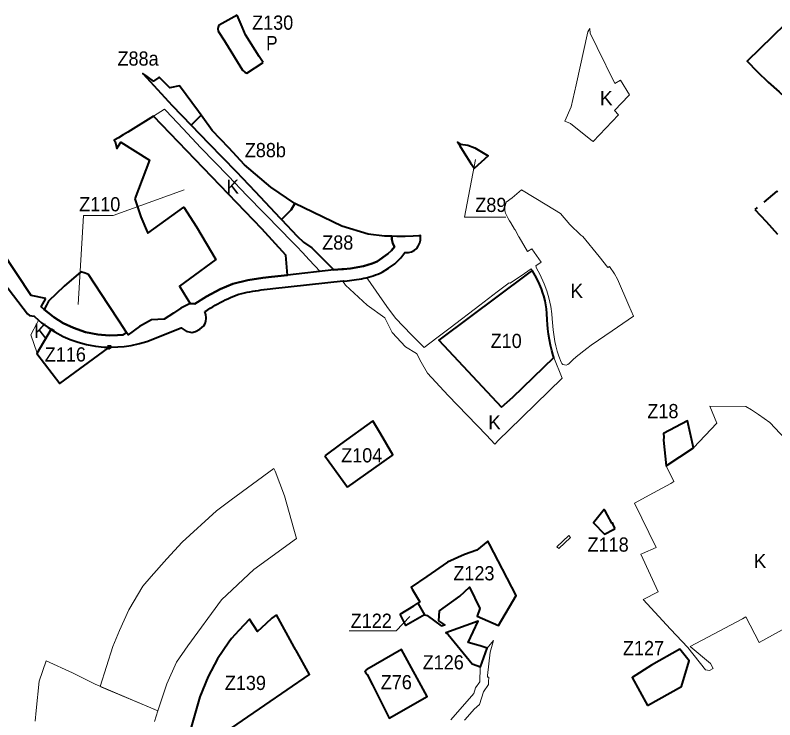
# Model space of a CAD drawing. Extents: x -650276 to -642489, y -1074311 to -1066658.
# Drawn here: x -647428 to -646145, y -1072934 to -1071744 of the extents above; entities that cross this region are included whole.
import ezdxf

# ---------------------------------------------------------------- set-up
doc = ezdxf.new("R2010")
doc.units = 0
doc.header["$LTSCALE"] = 9.6
doc.linetypes.add('MEDIUM_DASHED', pattern=[4.5, 3, -1.5])
for name, color, linetype, lineweight in [('2', 7, 'Continuous', 40), ('4', 7, 'Continuous', 40), ('44', 7, 'Continuous', 40), ('45', 7, 'Continuous', 40), ('46', 7, 'Continuous', 13), ('47', 7, 'Continuous', 13), ('48', 7, 'Continuous', 35), ('59', 7, 'Continuous', 13), ('60', 7, 'Continuous', 35), ('61', 7, 'MEDIUM_DASHED', 40)]:
    doc.layers.add(name, color=color, linetype=linetype, lineweight=lineweight)

msp = doc.modelspace()

# ---------------------------------------------------------------- linework, layer by layer
at = {"layer": '2'}
for points in [[(-647053.43, -1071743.63), (-647083.97, -1071760.74), (-647084.95, -1071761.98), (-647085.71, -1071763.75), (-647086.19, -1071766.95), (-647085.25, -1071770.69), (-647074.99, -1071786.99), (-647073.19, -1071789.9), (-647044.12, -1071836.68)], [(-647009.514, -1071823.81), (-647016.12, -1071813.35), (-647039.14, -1071776.9), (-647044.83, -1071763.37), (-647053.43, -1071743.63)], [(-647044.12, -1071836.68), (-647040.2, -1071839.6), (-647037.23, -1071841.82), (-647009.514, -1071823.81)], [(-647184.81, -1071848.61), (-647185.62, -1071849.12), (-647194.96, -1071854.93), (-647205.62, -1071847.24), (-647212.66, -1071842.15), (-647163.08, -1071896.13), (-647131.146, -1071929.146)], [(-647131.146, -1071929.146), (-647114.479, -1071912.479), (-647118.79, -1071906.59), (-647151.07, -1071863.08), (-647167.15, -1071866.22), (-647184.81, -1071848.61)], [(-646996.8, -1072034.35), (-647040.89, -1071996.58), (-647067.53, -1071967.54), (-647095.51, -1071938.39), (-647114.479, -1071912.479), (-647131.146, -1071929.146), (-647101.07, -1071960.24)], [(-647101.07, -1071960.24), (-647055.16, -1072007.74), (-647023.04, -1072041.63), (-646981.35, -1072085.77), (-646978.602, -1072088.66), (-646962.041, -1072072.379), (-646956.04, -1072061.95), (-646996.8, -1072034.35)], [(-646737.05, -1072756.4), (-646732.5, -1072757.63), (-646708.65, -1072775.02), (-646702.45, -1072773.39), (-646712.46, -1072766.76), (-646711.79, -1072750.02), (-646677.39, -1072724.85), (-646660.89, -1072709.97), (-646643.36, -1072746.04), (-646647.93, -1072759.01), (-646612.11, -1072774.56), (-646581.92, -1072723.91), (-646589.37, -1072709.83), (-646605.23, -1072679.37), (-646627.32, -1072636.95), (-646629.86, -1072632.07), (-646648.27, -1072647.48), (-646669.6, -1072654.53), (-646697.89, -1072667.65)], [(-646697.89, -1072667.65), (-646732.95, -1072691.68), (-646759.491, -1072709.878), (-646757.5, -1072713.3), (-646747.87, -1072729.85), (-646744.94, -1072734.88), (-646748.3, -1072737.01), (-646737.05, -1072756.4)], [(-646653.02, -1072806.07), (-646663.07, -1072803.04), (-646663.07, -1072803.04), (-646646.12, -1072767.32), (-646646.31, -1072767.388), (-646701.12, -1072787.08), (-646697.09, -1072790.03), (-646656.36, -1072839.08)], [(-646656.36, -1072839.08), (-646642.404, -1072844.195), (-646631.08, -1072812.68), (-646643.01, -1072809.08), (-646651.11, -1072806.64), (-646653.02, -1072806.07)]]:
    msp.add_lwpolyline(points, dxfattribs=at)
for points in [[(-646778.2, -1072755.19), (-646755.1, -1072741.28), (-646748.3, -1072737.01), (-646737.05, -1072756.4), (-646768.74, -1072774.78)], [(-646360.22, -1072909.57), (-646303.02, -1072877.74), (-646289.63, -1072834.04), (-646305.56, -1072814.43), (-646353.25, -1072841.63), (-646385.86, -1072862.59)]]:
    msp.add_lwpolyline(points, close=True, dxfattribs=at)
at = {"layer": '4'}
for points in [[(-646987.154, -1072756.377), (-646995.02, -1072762.45), (-647005.249, -1072771.938), (-647019.06, -1072784.57), (-647032.7, -1072763.68), (-647050.492, -1072782.771)], [(-646954.7, -1072815.232), (-646957.105, -1072810.92), (-646987.154, -1072756.377)], [(-647050.492, -1072782.771), (-647063.04, -1072796.74), (-647067.22, -1072802.77), (-647086.65, -1072830.76), (-647102.38, -1072860.7), (-647116.33, -1072895.3)], [(-647136.39, -1072968.63), (-647110.32, -1072964.56), (-647107.01, -1072964.04), (-647105.4, -1072963.84), (-647082.36, -1072960.95), (-646931.1, -1072857.55), (-646954.51, -1072815.63), (-646954.7, -1072815.232)], [(-647116.33, -1072895.3), (-647132.47, -1072950.4), (-647136.39, -1072968.63)]]:
    msp.add_lwpolyline(points, dxfattribs=at)
at = {"layer": '44'}
msp.add_line((-646978.602, -1072088.66), (-646951.95, -1072116.84), dxfattribs=at)
msp.add_lwpolyline([(-646652.18, -1071967.73), (-646629.655, -1071981.343), (-646653.198, -1072002.544), (-646657.32, -1071995.98), (-646658.79, -1071993.62), (-646669.31, -1071976.77), (-646676.79, -1071964.97), (-646681.07, -1071958.16), (-646675.99, -1071961.64), (-646663.87, -1071963.26)], close=True, dxfattribs=at)
at = {"layer": '44', "lineweight": 13}
msp.add_lwpolyline([(-646599.686, -1072084.891), (-646669.193, -1072084.891), (-646650.508, -1071987.658)], dxfattribs=at)
msp.add_lwpolyline([(-646599.686, -1072084.891), (-646669.193, -1072084.891), (-646650.508, -1071987.658)], dxfattribs=at)
at = {"layer": '44'}
for points in [[(-646790.432, -1072129.195), (-646791.977, -1072122.305), (-646791.84, -1072117.172), (-646804.27, -1072116.98), (-646832.01, -1072113.66), (-646876.83, -1072100.12), (-646941.054, -1072069.172), (-646956.04, -1072061.95), (-646962.041, -1072072.379), (-646978.602, -1072088.66)], [(-646951.95, -1072116.84), (-646941.45, -1072126.84), (-646927.14, -1072136.74), (-646891.05, -1072172.79), (-646890.044, -1072174.056), (-646876.712, -1072172.592), (-646873.495, -1072172.799), (-646862.09, -1072171.444), (-646840.102, -1072167.623), (-646825.169, -1072163.164), (-646816.74, -1072159.571), (-646799, -1072147), (-646792.58, -1072140.847), (-646787.481, -1072134.643), (-646790.432, -1072129.195)], [(-646808.466, -1072177.78), (-646797.713, -1072171.151), (-646787.223, -1072163.402), (-646777.129, -1072153.576), (-646770.057, -1072144.677), (-646763.959, -1072144.535), (-646758.736, -1072143.137), (-646753.929, -1072140.612), (-646750.164, -1072137.467), (-646747.39, -1072134.069), (-646744.554, -1072128.415), (-646743.411, -1072123.612), (-646743.596, -1072115.985), (-646746.547, -1072116.221), (-646756.298, -1072117), (-646769.668, -1072117.517), (-646783.449, -1072117.302), (-646791.84, -1072117.172)], [(-646791.84, -1072117.172), (-646791.977, -1072122.305), (-646790.432, -1072129.195)], [(-646790.432, -1072129.195), (-646787.481, -1072134.643), (-646792.58, -1072140.847), (-646799, -1072147), (-646816.74, -1072159.571), (-646825.169, -1072163.164), (-646840.102, -1072167.623), (-646862.09, -1072171.444), (-646873.495, -1072172.799), (-646876.712, -1072172.592), (-646890.044, -1072174.056), (-646968.503, -1072182.672)], [(-647376.68, -1072222.29), (-647401.221, -1072217.342), (-647451.21, -1072142.08), (-647452.23, -1072134.91)], [(-647475.57, -1072159.74), (-647447.73, -1072195.72), (-647407.34, -1072247.93)], [(-646835.538, -1072187.097), (-646831.517, -1072186.103), (-646827.501, -1072184.997), (-646823.496, -1072183.769), (-646819.509, -1072182.408), (-646815.549, -1072180.906), (-646811.621, -1072179.254), (-646808.466, -1072177.78)], [(-646968.503, -1072182.672), (-646995.137, -1072185.597), (-647010.148, -1072187.308), (-647035.515, -1072191.104), (-647060.973, -1072197.439), (-647082.249, -1072206.591), (-647104.989, -1072219.005), (-647124.81, -1072231.168), (-647133, -1072230.754), (-647148.71, -1072238.76)], [(-647017.46, -1072208.427), (-647012.612, -1072207.773), (-647007.734, -1072207.162), (-647002.826, -1072206.583), (-646997.894, -1072206.024), (-646992.937, -1072205.475), (-646874.517, -1072192.471), (-646871.271, -1072192.675)], [(-646871.271, -1072192.675), (-646867.371, -1072192.234), (-646867.32, -1072192.228), (-646863.448, -1072191.771), (-646859.506, -1072191.276), (-646855.545, -1072190.741), (-646851.567, -1072190.155)], [(-646851.567, -1072190.155), (-646847.575, -1072189.507), (-646843.569, -1072188.789), (-646843.535, -1072188.782), (-646839.556, -1072187.988), (-646835.538, -1072187.097)], [(-647108.131, -1072244.373), (-647103.164, -1072241.306), (-647098.944, -1072238.718), (-647094.737, -1072236.177), (-647090.531, -1072233.695), (-647086.322, -1072231.285), (-647082.102, -1072228.962), (-647077.867, -1072226.739), (-647073.611, -1072224.631), (-647069.33, -1072222.651), (-647064.868, -1072220.746), (-647054.841, -1072216.479), (-647050.344, -1072215.107), (-647045.786, -1072213.858), (-647041.174, -1072212.723), (-647036.512, -1072211.693), (-647031.807, -1072210.758), (-647027.061, -1072209.91), (-647022.278, -1072209.136), (-647017.46, -1072208.427)], [(-647240.55, -1072279.42), (-647246.206, -1072283.328), (-647255.671, -1072284.192), (-647269.579, -1072284.489), (-647288.769, -1072283.003), (-647309.416, -1072278.875), (-647330.032, -1072271.935), (-647347.382, -1072263.623), (-647363.317, -1072253.632), (-647363.786, -1072253.254), (-647379.422, -1072240.675), (-647384.567, -1072236.256), (-647376.68, -1072222.29)], [(-647148.71, -1072238.76), (-647160.91, -1072246.82), (-647176.7, -1072257.24), (-647198.3, -1072258.09), (-647218.35, -1072269.67), (-647237.6, -1072283.78), (-647240.55, -1072279.42)], [(-647407.34, -1072247.93), (-647404.45, -1072250.66), (-647396.25, -1072252.14), (-647389.072, -1072258.845)], [(-647389.072, -1072258.845), (-647383.813, -1072263.219), (-647372.858, -1072271.363), (-647361.521, -1072278.584), (-647347.369, -1072286.111)], [(-647205.975, -1072294.599), (-647148.171, -1072271.47), (-647139.697, -1072277.484), (-647130.12, -1072279.44), (-647123.774, -1072277.899)], [(-647123.774, -1072277.899), (-647116.323, -1072273.885), (-647109.812, -1072268.588)], [(-647347.369, -1072286.111), (-647335.382, -1072291.341), (-647321.953, -1072296.073), (-647308.157, -1072299.786), (-647292.715, -1072302.646), (-647278.108, -1072304.147), (-647271.395, -1072304.452), (-647269.52, -1072307.17), (-647265.793, -1072304.439)], [(-647265.793, -1072304.439), (-647255.16, -1072304.123), (-647244.428, -1072303.192), (-647232.368, -1072301.4), (-647218.5, -1072298.335), (-647205.975, -1072294.599)]]:
    msp.add_lwpolyline(points, dxfattribs=at)
msp.add_arc((-647130.12, -1072255.012), 24.428, 326.23773, 25.81772, dxfattribs=at)
at = {"layer": '45'}
msp.add_line((-646417.787, -1072612.168), (-646414.77, -1072610.61), dxfattribs=at)
for points in [[(-646102.04, -1071906.4), (-646068.317, -1071937.555), (-646062.91, -1071942.55), (-646002.93, -1071893.984), (-646026.64, -1071867.44), (-646043.49, -1071845.87), (-646077.32, -1071802.59), (-646087, -1071795), (-646104.5, -1071774.86), (-646122.16, -1071754.78), (-646127.12, -1071759.15), (-646127.84, -1071758.53), (-646191.57, -1071821.44), (-646174.69, -1071838.69), (-646156.59, -1071856.53), (-646137.74, -1071873.31)], [(-647226.41, -1072054.11), (-647219.64, -1072074.29), (-647216.23, -1072084.14), (-647204.78, -1072110.92), (-647204.38, -1072111.87), (-647143.76, -1072067.69), (-647122.33, -1072101.34), (-647089.54, -1072156.53), (-647134.17, -1072188.95), (-647151.05, -1072201.21), (-647138.65, -1072221.5), (-647133, -1072230.754), (-647124.81, -1072231.168), (-647104.989, -1072219.005), (-647082.249, -1072206.591), (-647060.973, -1072197.439), (-647035.515, -1072191.104), (-647010.148, -1072187.308), (-646995.137, -1072185.597), (-646968.503, -1072182.672), (-646971.283, -1072148.82), (-647011.762, -1072104.502), (-647194.903, -1071913.941), (-647238.1, -1071941), (-647245.71, -1071945.77), (-647253.67, -1071950.76), (-647261.12, -1071954.82), (-647259.7, -1071957.06), (-647256.53, -1071968.64), (-647253.85, -1071964.38), (-647249.92, -1071958.12), (-647201.53, -1071988.71)], [(-647226.41, -1072054.11), (-647219.64, -1072074.29), (-647216.23, -1072084.14), (-647204.78, -1072110.92), (-647204.38, -1072111.87), (-647143.76, -1072067.69), (-647122.33, -1072101.34), (-647089.54, -1072156.53), (-647134.17, -1072188.95), (-647151.05, -1072201.21), (-647138.65, -1072221.5), (-647133, -1072230.754), (-647124.81, -1072231.168), (-647104.989, -1072219.005), (-647082.249, -1072206.591), (-647060.973, -1072197.439), (-647035.515, -1072191.104), (-647010.148, -1072187.308), (-646995.137, -1072185.597), (-646968.503, -1072182.672), (-646971.283, -1072148.82), (-647011.762, -1072104.502), (-647194.903, -1071913.941), (-647238.1, -1071941), (-647245.71, -1071945.77), (-647253.67, -1071950.76), (-647261.12, -1071954.82), (-647259.7, -1071957.06), (-647256.53, -1071968.64), (-647253.85, -1071964.38), (-647249.92, -1071958.12), (-647201.53, -1071988.71)], [(-647246.563, -1072270.214), (-647251.85, -1072262.12), (-647271.38, -1072232.23), (-647304.32, -1072181.81), (-647310.33, -1072179.58), (-647317.33, -1072176.99), (-647345.42, -1072201.58), (-647372.1, -1072226.89), (-647375.551, -1072233.387), (-647379.422, -1072240.675), (-647363.317, -1072253.632), (-647347.382, -1072263.623), (-647330.032, -1072271.935), (-647309.416, -1072278.875), (-647288.769, -1072283.003), (-647269.579, -1072284.489), (-647255.671, -1072284.192), (-647246.206, -1072283.328), (-647240.55, -1072279.42)], [(-647246.563, -1072270.214), (-647251.85, -1072262.12), (-647271.38, -1072232.23), (-647304.32, -1072181.81), (-647310.33, -1072179.58), (-647317.33, -1072176.99), (-647345.42, -1072201.58), (-647372.1, -1072226.89), (-647375.551, -1072233.387), (-647379.422, -1072240.675), (-647363.317, -1072253.632), (-647347.382, -1072263.623), (-647330.032, -1072271.935), (-647309.416, -1072278.875), (-647288.769, -1072283.003), (-647269.579, -1072284.489), (-647255.671, -1072284.192), (-647246.206, -1072283.328), (-647240.55, -1072279.42)], [(-646606.848, -1072405.785), (-646587.666, -1072389.082), (-646518.208, -1072321.92), (-646519.417, -1072318.408), (-646522.007, -1072309.932), (-646524.282, -1072300.849), (-646526, -1072292.201), (-646527.5, -1072282.657), (-646528.566, -1072273.308), (-646529.182, -1072265.941), (-646529.607, -1072258.124), (-646530.188, -1072247.442), (-646530.892, -1072239.747), (-646531.93, -1072232.861), (-646533.286, -1072226.031), (-646535.344, -1072217.844), (-646536.772, -1072213.218), (-646539.168, -1072206.122), (-646539.168, -1072206.122), (-646542.484, -1072197.985), (-646546.09, -1072190.428), (-646549.793, -1072183.38), (-646554.56, -1072175.629), (-646555.051, -1072174.933), (-646563.299, -1072181.091), (-646710.684, -1072291.133), (-646712.634, -1072292.59)], [(-646333.34, -1072461.67), (-646328.45, -1072504.81), (-646282.47, -1072474.34), (-646292.44, -1072428.89), (-646333.33, -1072450.12), (-646332.68, -1072456.19)], [(-646333.34, -1072461.67), (-646328.45, -1072504.81), (-646282.47, -1072474.34), (-646292.44, -1072428.89), (-646333.33, -1072450.12), (-646332.68, -1072456.19)], [(-646837.81, -1072851.3), (-646836.5, -1072853.76), (-646833.67, -1072857.15), (-646824.89, -1072874.66), (-646796.68, -1072930.92), (-646732.28, -1072894.29), (-646775.85, -1072815.39), (-646834.08, -1072849.15)], [(-646837.81, -1072851.3), (-646836.5, -1072853.76), (-646833.67, -1072857.15), (-646824.89, -1072874.66), (-646796.68, -1072930.92), (-646732.28, -1072894.29), (-646775.85, -1072815.39), (-646834.08, -1072849.15)]]:
    msp.add_lwpolyline(points, close=True, dxfattribs=at)
for points in [[(-647362.702, -1072277.035), (-647367.686, -1072273.861), (-647391.761, -1072315.201), (-647353.041, -1072365.971), (-647270.701, -1072305.621), (-647266.974, -1072302.89), (-647272.576, -1072302.903)], [(-646824.42, -1072428.58), (-646878.91, -1072468.54), (-646905.18, -1072487.8)], [(-646824.42, -1072428.58), (-646878.91, -1072468.54), (-646905.18, -1072487.8)], [(-646867.283, -1072540.984), (-646791.569, -1072487.198), (-646790.354, -1072486.136), (-646810.77, -1072451.09), (-646824.42, -1072428.58)], [(-646867.283, -1072540.984), (-646791.569, -1072487.198), (-646790.354, -1072486.136), (-646810.77, -1072451.09), (-646824.42, -1072428.58)], [(-646905.18, -1072487.8), (-646898.1, -1072498.02), (-646893.64, -1072504.45), (-646867.283, -1072540.984)], [(-646905.18, -1072487.8), (-646898.1, -1072498.02), (-646893.64, -1072504.45), (-646867.283, -1072540.984)], [(-646420.36, -1072601.78), (-646427.95, -1072588.07), (-646432.57, -1072579.75), (-646433.36, -1072578.45), (-646451.458, -1072601.008), (-646433.024, -1072620.04), (-646417.787, -1072612.168)], [(-646414.77, -1072610.61), (-646419.11, -1072602.03), (-646419.47, -1072601.31), (-646419.02, -1072604.18), (-646420.36, -1072601.78)]]:
    msp.add_lwpolyline(points, dxfattribs=at)
msp.add_arc((-646767.624, -1072120.384), 24.428, 264.28146, 264.89913, dxfattribs=at)
msp.add_arc((-646767.624, -1072120.384), 24.428, 264.28146, 264.89913, dxfattribs=at)
at = {"layer": '46'}
for points in [[(-647321.863, -1072232.262), (-647313.149, -1072082.081), (-647262.801, -1072082.081), (-647142.741, -1072038.48)], [(-647321.863, -1072232.262), (-647313.149, -1072082.081), (-647262.801, -1072082.081), (-647142.741, -1072038.48)], [(-646864.278, -1072783.783), (-646784.878, -1072783.783), (-646761.687, -1072759.411)]]:
    msp.add_lwpolyline(points, dxfattribs=at)
at = {"layer": '47'}
for p, q in [((-646490.111, -1071926.754), (-646453.04, -1071956.3)), ((-647391.346, -1072314.489), (-647368.024, -1072274.442))]:
    msp.add_line(p, q, dxfattribs=at)
for points in [[(-646453.04, -1071956.3), (-646451.87, -1071956.88), (-646409.4, -1071912.17), (-646416.2, -1071904.81), (-646391.83, -1071879.32), (-646390.732, -1071878.171), (-646405.99, -1071853.26), (-646415.46, -1071859.05), (-646445.115, -1071798.418), (-646456.96, -1071774.2), (-646457.52, -1071765.98), (-646461.09, -1071771.76), (-646480.81, -1071861.18), (-646489.34, -1071898.61), (-646499.741, -1071922.455), (-646490.111, -1071926.754)], [(-646913.373, -1072176.618), (-646931.653, -1072156.802), (-646942.78, -1072144.74), (-646952.48, -1072134.22), (-646964.8, -1072121.83), (-646977.59, -1072108.96), (-646978.45, -1072108.09), (-647036.8, -1072048.41), (-647068.31, -1072015.68), (-647114.59, -1071967.77), (-647145.38, -1071935), (-647173.14, -1071905.45), (-647174.57, -1071904.06), (-647176.32, -1071902.3), (-647194.902, -1071913.942), (-647011.762, -1072104.502)], [(-646507.28, -1072078.4), (-646530.073, -1072064.559), (-646573.05, -1072038.46), (-646588.75, -1072052.06), (-646598.827, -1072059.244), (-646599.86, -1072063.71), (-646601, -1072067.55), (-646601.42, -1072071.01), (-646601.16, -1072074.07), (-646600.8, -1072075.94), (-646600.22, -1072077.86), (-646598.67, -1072081.55), (-646595.86, -1072086.82), (-646593.13, -1072091.01), (-646591.02, -1072094.4), (-646585.08, -1072104.81), (-646583.9, -1072106.42), (-646577.41, -1072117.76), (-646577.08, -1072118.7), (-646563.11, -1072143.03), (-646555.49, -1072138.17), (-646539.94, -1072160.83), (-646548.676, -1072166.737)], [(-646472.72, -1072115.38), (-646491.69, -1072097.45), (-646507.28, -1072078.4)], [(-647011.762, -1072104.502), (-646971.283, -1072148.82), (-646968.503, -1072182.672), (-646913.373, -1072176.618)], [(-646426.98, -1072169.74), (-646441.961, -1072151.281), (-646469.41, -1072117.44), (-646472.72, -1072115.38)], [(-646548.676, -1072166.737), (-646547.606, -1072170.835), (-646541.822, -1072181.102), (-646534.527, -1072197.411), (-646530.167, -1072209.31), (-646526.798, -1072221.011), (-646523.628, -1072235.883)], [(-646415.84, -1072180.43), (-646424.56, -1072167.96), (-646426.98, -1072169.74)], [(-646391.77, -1072233.91), (-646410.68, -1072189.36), (-646415.84, -1072180.43)], [(-646523.628, -1072235.883), (-646523.628, -1072235.883), (-646521.646, -1072248.378), (-646521.051, -1072256.707), (-646519.756, -1072274.861), (-646518.079, -1072287.051), (-646516.692, -1072294.983), (-646515.305, -1072301.925), (-646512.729, -1072311.048), (-646509.954, -1072319.377), (-646506.189, -1072329.889), (-646504.802, -1072331.971), (-646503.018, -1072333.459), (-646500.244, -1072334.45), (-646497.569, -1072334.55), (-646494.794, -1072333.558), (-646492.813, -1072332.07), (-646486.273, -1072325.526), (-646480.923, -1072320.667), (-646462.79, -1072306.784), (-646455.557, -1072301.131), (-646420.085, -1072276.737), (-646384.056, -1072252.138), (-646391.77, -1072233.91)], [(-647389.072, -1072258.845), (-647391.3, -1072263.04), (-647401.88, -1072283.4), (-647391.346, -1072314.489)], [(-647368.024, -1072274.442), (-647372.858, -1072271.363), (-647372.858, -1072271.363), (-647383.813, -1072263.219), (-647389.072, -1072258.845)], [(-645999.622, -1072714.927), (-646006.66, -1072681.4), (-646019.16, -1072642.35), (-646030.17, -1072612.31), (-646043.87, -1072578.12), (-646056.42, -1072556.49), (-646075.82, -1072525.54), (-646110.61, -1072477.49), (-646153.49, -1072431.54), (-646172.81, -1072418.2), (-646184.449, -1072410.256), (-646194.19, -1072404.62), (-646254.75, -1072404.25), (-646243.17, -1072432.88), (-646282.47, -1072474.34), (-646328.45, -1072504.81), (-646315.452, -1072531.573)], [(-646315.452, -1072531.573), (-646320.62, -1072534.6), (-646350.18, -1072550.59), (-646382.41, -1072568.01), (-646345.6, -1072642.55), (-646368.51, -1072652.81), (-646371.66, -1072654.2), (-646342.08, -1072717.43), (-646367.72, -1072730.68), (-646321.171, -1072780.535), (-646292.17, -1072811.6), (-646261.97, -1072849.66), (-646255.39, -1072850.83), (-646249.04, -1072847.16), (-646253.56, -1072838.8), (-646288.27, -1072810.22), (-646199.72, -1072763.1), (-646194.296, -1072760.193)], [(-646194.296, -1072760.193), (-646171.72, -1072803.51), (-646052.58, -1072737.82), (-646037.23, -1072736.38), (-646022.4, -1072741.58), (-646003.22, -1072757.85), (-645988.43, -1072769.93), (-645983.22, -1072780.88), (-645986.24, -1072788.33), (-645986.359, -1072796.127)], [(-646669.198, -1072934.569), (-646668.09, -1072933.43), (-646652.76, -1072915.66), (-646644.069, -1072908.218), (-646644.061, -1072908.209), (-646644.059, -1072908.208), (-646637.2, -1072886.57), (-646628.7, -1072874.5), (-646628.58, -1072869.88), (-646628.36, -1072861.71), (-646630.76, -1072861.61), (-646630.57, -1072859.99), (-646630.45, -1072858.93), (-646625.91, -1072819.66), (-646620.27, -1072799.95), (-646631.08, -1072812.68), (-646640.313, -1072838.394), (-646642.404, -1072844.195), (-646642.39, -1072844.2), (-646642.438, -1072844.29), (-646642.939, -1072845.68), (-646643.574, -1072869.57), (-646650.798, -1072879.828), (-646653.846, -1072889.44), (-646692.432, -1072934.135)], [(-647192.93, -1072936.82), (-647187.445, -1072918.804), (-647293.317, -1072873.549), (-647293.351, -1072873.533), (-647331.82, -1072854.49), (-647375.92, -1072833.99), (-647387.64, -1072868.69), (-647392.96, -1072918.277), (-647394.87, -1072936.08)]]:
    msp.add_lwpolyline(points, dxfattribs=at)
for points in [[(-646587.666, -1072389.082), (-646606.848, -1072405.785), (-646712.634, -1072292.59), (-646563.299, -1072181.091), (-646556.591, -1072176.083), (-646555.051, -1072174.933), (-646556.693, -1072172.16), (-646568.051, -1072179.84), (-646592.2, -1072196.17), (-646593.85, -1072195.48), (-646614.075, -1072210.952), (-646643.55, -1072233.5), (-646693.58, -1072271.606), (-646716.167, -1072288.809), (-646737.449, -1072305.019), (-646738.951, -1072303.49), (-646758.684, -1072283.41), (-646785.958, -1072255.505), (-646800.76, -1072235.668), (-646813.508, -1072217.089), (-646813.516, -1072217.078), (-646832.718, -1072189.697), (-646834.279, -1072186.818), (-646835.199, -1072187.013), (-646835.538, -1072187.097), (-646839.556, -1072187.988), (-646843.535, -1072188.782), (-646843.569, -1072188.789), (-646847.575, -1072189.507), (-646851.567, -1072190.155), (-646855.545, -1072190.741), (-646859.506, -1072191.276), (-646863.448, -1072191.771), (-646867.32, -1072192.228), (-646867.371, -1072192.234), (-646871.271, -1072192.675), (-646873.131, -1072192.558), (-646875.509, -1072192.58), (-646870.21, -1072199.51), (-646833.75, -1072233.32), (-646803.98, -1072254.74), (-646791.59, -1072279.78), (-646769.24, -1072303.65), (-646750.58, -1072315.02), (-646750.12, -1072315.82), (-646742.32, -1072329.62), (-646731.82, -1072348.2), (-646696.83, -1072385.81), (-646632.356, -1072453.247), (-646618.158, -1072468.098), (-646611.091, -1072460.994), (-646594.606, -1072444.422), (-646594.561, -1072444.38), (-646504.244, -1072357.026), (-646518.208, -1072321.92)], [(-647284.75, -1072877.79), (-647282.31, -1072878.82), (-647192.718, -1072916.582), (-647187.445, -1072918.804), (-647172.48, -1072872.92), (-647155.72, -1072836.46), (-647136.69, -1072808.98), (-647079.74, -1072731.1), (-647025.04, -1072679.96), (-646953.2, -1072627.45), (-646957.5, -1072612.09), (-646973.68, -1072555.68), (-646989.01, -1072513.62), (-646991.24, -1072509.24), (-647063.38, -1072562.42), (-647088.397, -1072580.865), (-647088.4, -1072580.868), (-647146.21, -1072634.02), (-647172.36, -1072661.69), (-647198.77, -1072691.71), (-647212.92, -1072708.05), (-647236.54, -1072748.09), (-647252.29, -1072783.24), (-647263.58, -1072809.97)], [(-646493.229, -1072622.74), (-646513.209, -1072641.935), (-646510.28, -1072644.42), (-646490.11, -1072626.15)]]:
    msp.add_lwpolyline(points, close=True, dxfattribs=at)
at = {"layer": '61'}
msp.add_lwpolyline([(-646141.703, -1072041.072), (-646178.915, -1072071.95), (-646159.66, -1072092.31), (-646123.06, -1072133.18), (-646095.44, -1072162.47), (-646067.08, -1072201.18), (-646008.065, -1072293.22), (-645928.101, -1072218.151), (-646005.793, -1072151.499)], close=True, dxfattribs=at)

# ---------------------------------------------------------------- texts
at = {"layer": '2', "width": 0.95}
for s, p in [('Z130', (-647028.202, -1071768.178)), ('Z88a', (-647255.564, -1071828.861)), ('Z88b', (-647040.507, -1071983.505)), ('Z123', (-646688.261, -1072698.34)), ('Z122', (-646861.605, -1072778.534)), ('Z127', (-646401.702, -1072824.699)), ('Z126', (-646740.041, -1072848.718))]:
    msp.add_text(s, height=24, dxfattribs=at).set_placement(p)
at = {"layer": '44', "width": 0.95}
for s, p in [('Z89', (-646651.144, -1072076.059)), ('Z89', (-646651.144, -1072076.059)), ('Z88', (-646909.741, -1072139.634)), ('Z88', (-646909.741, -1072139.634))]:
    msp.add_text(s, height=24, dxfattribs=at).set_placement(p)
at = {"layer": '46', "width": 0.95}
for s, p in [('Z110', (-647320.328, -1072074.974)), ('Z110', (-647320.328, -1072074.974)), ('Z10', (-646625.207, -1072305.81)), ('Z116', (-647378.432, -1072328.636)), ('Z18', (-646360.479, -1072424.402)), ('Z104', (-646877.745, -1072499.058)), ('Z104', (-646877.745, -1072499.058)), ('Z118', (-646461.466, -1072649.857)), ('Z76', (-646810.899, -1072882.315)), ('Z76', (-646810.899, -1072882.315))]:
    msp.add_text(s, height=24, dxfattribs=at).set_placement(p)
at = {"layer": '48'}
for p in [(-646440.579, -1071895.779), (-647071.498, -1072045.307), (-646490.42, -1072221.403), (-647396.507, -1072288.9), (-646629.338, -1072443.411), (-646180.786, -1072677.559), (-646180.786, -1072677.559)]:
    msp.add_text('K', height=24, dxfattribs=at).set_placement(p)
at = {"layer": '59', "width": 0.95}
msp.add_text('Z139', height=24, dxfattribs=at).set_placement((-647074.31, -1072883.554))
at = {"layer": '60', "width": 0.9}
msp.add_text('P', height=24, dxfattribs=at).set_placement((-647004.438, -1071802.773))

doc.saveas('drawing.dxf')
